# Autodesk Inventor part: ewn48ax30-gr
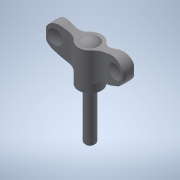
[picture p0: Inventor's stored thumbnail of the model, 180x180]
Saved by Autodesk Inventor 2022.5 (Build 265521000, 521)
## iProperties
Created: 2016-12
Part Number: ewn48ax30-gr
Material: 一般
Document SubType Name: Modeling
Designer: imaocorp
Density: 1 g/cm^3
Appearance: 既定
Author: imaocorp
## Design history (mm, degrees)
node "ewn48ax30-gr.x_t1"
node "ewn48ax30-gr"
node "Base1"
